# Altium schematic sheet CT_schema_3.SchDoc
size 284 x 147 mm
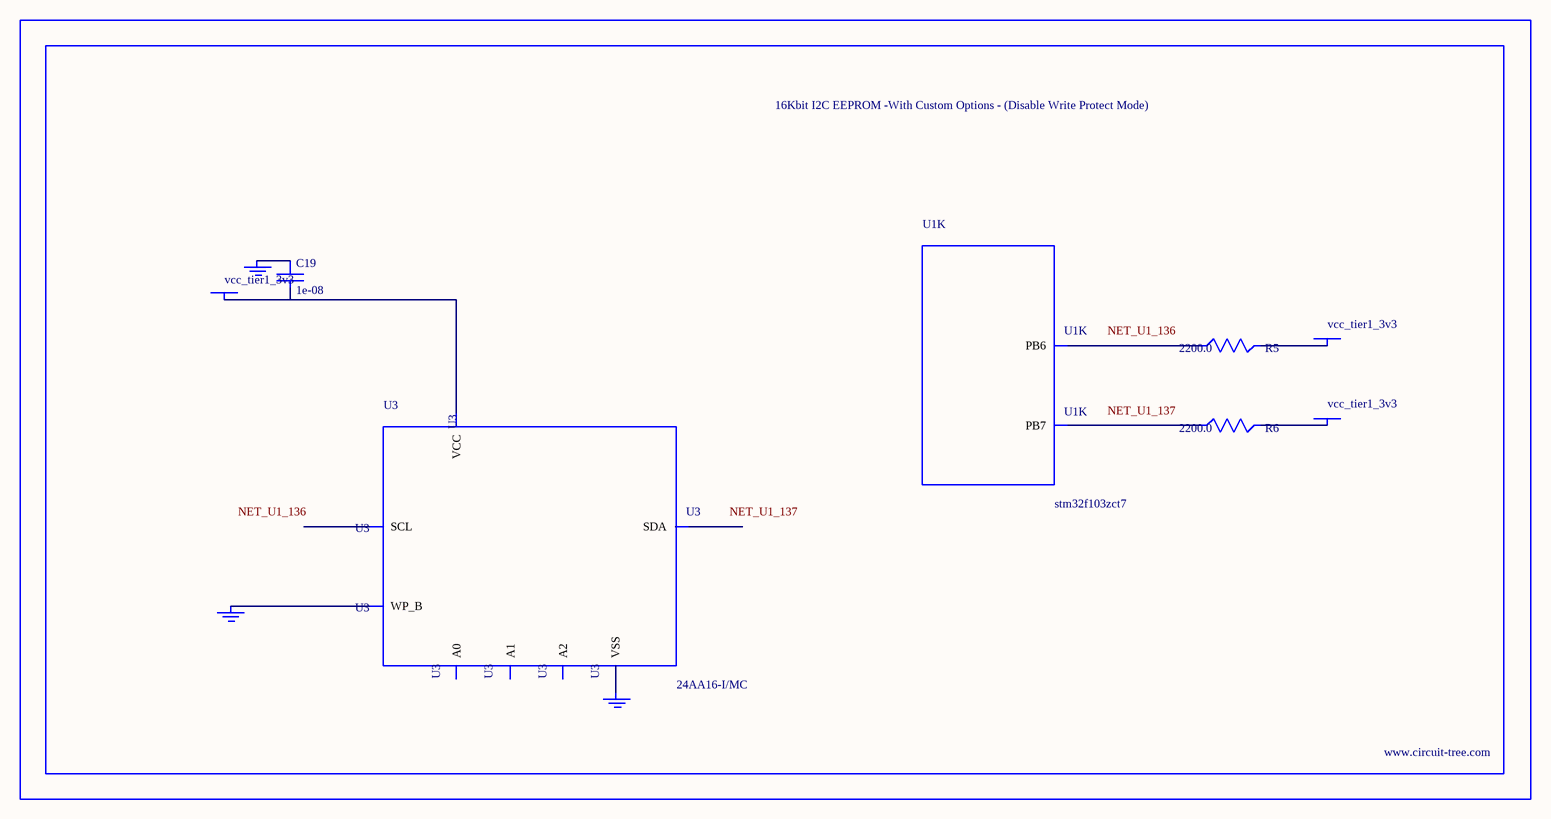
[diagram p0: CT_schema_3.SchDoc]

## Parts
BORDER2  (no value)
C19  1e-08  [C0402]
GND_INSTANCE_2_0  (no value)
GND_INSTANCE_2_1  (no value)
GND_INSTANCE_2_2  (no value)
POWER_INSTANCE_2_0  vcc_tier1_3v3
POWER_INSTANCE_2_1  vcc_tier1_3v3
POWER_INSTANCE_2_2  vcc_tier1_3v3
R5  2200.0  [R0603]
R6  2200.0  [R0603]
U1  stm32f103zct7  [LQFP144]  (part K of 13)
U3  24AA16-I/MC  [TDFN-8/6MM]

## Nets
NetC19_1: C19.1 GND_INSTANCE_2_1.0(GND)
NetC19_2: C19.2 POWER_INSTANCE_2_0.0(PWR) U3.8(VCC)
NetGND_INSTANCE_2_0_0: GND_INSTANCE_2_0.0(GND) U3.7(WP_B)
NetGND_INSTANCE_2_2_0: GND_INSTANCE_2_2.0(GND) U3.4(VSS)
NetPOWER_INSTANCE_2_1_0: POWER_INSTANCE_2_1.0(PWR) R5.2
NetPOWER_INSTANCE_2_2_0: POWER_INSTANCE_2_2.0(PWR) R6.2
NetR5_1: R5.1 U1.136(PB6)
NetR6_1: R6.1 U1.137(PB7)

Not connected (* = marked no-connect by the designer): U3 1(A0) 2(A1) 3(A2) 5(SDA) 6(SCL)

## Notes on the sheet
- Labels drawn without touching a wire or pin: NET_U1_136, NET_U1_137

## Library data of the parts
BORDER2 = BORDER_PAGE2
C19 = C0402C103K3RAC
GND_INSTANCE_2_0-GND_INSTANCE_2_2 = GND
POWER_INSTANCE_2_0-POWER_INSTANCE_2_2 = PWR
R5 R6 = RC0603JR-072K2L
